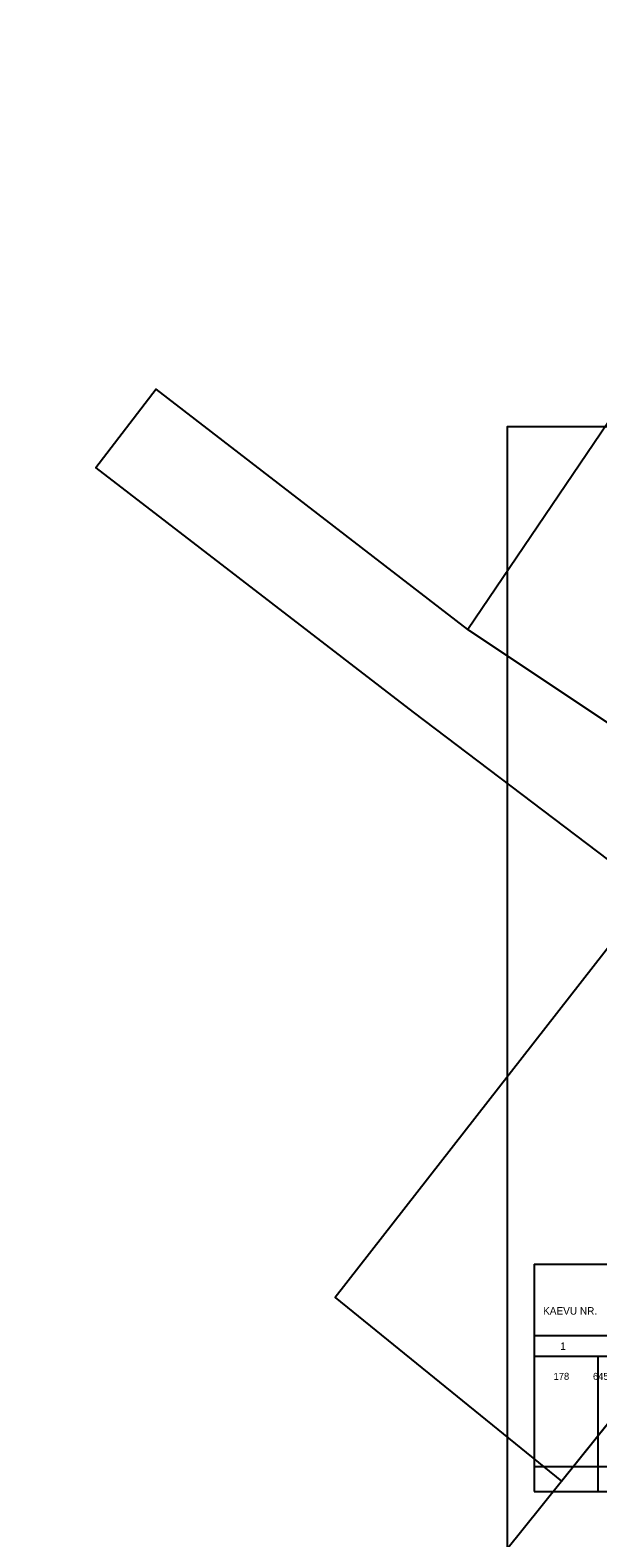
# Model space of a CAD drawing. Extents: x 640876 to 641182, y 6455704 to 6455993.
# Drawn here: x 640876.4 to 640933.2, y 6455818.5 to 6455969.2 of the extents above; entities that cross this region are included whole.
import ezdxf

# ---------------------------------------------------------------- set-up
doc = ezdxf.new("R2010")
doc.units = 0
for name, color, linetype in [('ABIJOONIS', 7, 'Continuous'), ('PIIR', 7, 'Continuous'), ('VORMISTUS', 7, 'Continuous')]:
    doc.layers.add(name, color=color, linetype=linetype)

msp = doc.modelspace()

# ---------------------------------------------------------------- linework, layer by layer
at = {"layer": 'ABIJOONIS'}
for p, q in [((640926.8, 6455845.85), (640977.48, 6455845.85)), ((640926.8, 6455845.85), (640926.8, 6455836.65)), ((640926.8, 6455838.74), (640975.11, 6455838.74)), ((640926.8, 6455836.65), (641014.84, 6455836.65)), ((640926.8, 6455836.65), (640926.8, 6455823.15)), ((640933.15, 6455836.65), (640933.15, 6455823.15)), ((640926.8, 6455825.65), (641014.8, 6455825.65)), ((640926.8, 6455825.65), (641014.8, 6455825.65)), ((640926.8, 6455823.15), (641014.8, 6455823.15))]:
    msp.add_line(p, q, dxfattribs=at)
at = {"layer": 'PIIR'}
for points in [[(640960.73, 6455969.25), (640920.16, 6455909.31), (640971.01, 6455875.38), (640993.57, 6455904.12), (640970.23, 6455922.96), (640989.11, 6455946.27)], [(640971.01, 6455875.38), (640920.16, 6455909.31), (640889.02, 6455933.34), (640882.97, 6455925.5), (640914.68, 6455901.06), (640938.5, 6455883.04), (640962.33, 6455865.02)], [(640962.33, 6455865.02), (640938.49, 6455883.03), (640906.91, 6455842.53), (640929.52, 6455824.17)]]:
    msp.add_lwpolyline(points, close=True, dxfattribs=at)
msp.add_lwpolyline([(641037.5, 6455958.58), (641024.93, 6455943.02), (641012.36, 6455927.46), (640993.57, 6455904.12), (640971.01, 6455875.38), (640962.33, 6455865.02), (640876.41, 6455757.97), (640888.17, 6455749.25), (640894.56, 6455746.37), (640902.45, 6455758.84), (640915.55, 6455775.13), (640928.34, 6455790.92), (640960.9, 6455766.7), (640964.64, 6455771.22), (640941.6, 6455788.51), (640929.99, 6455798.13), (640933.13, 6455802.02), (640952.64, 6455826.1), (640977.72, 6455857.07), (640984.64, 6455865.92), (641005.01, 6455891.09), (641032.25, 6455870.2), (641049.71, 6455856.81)], dxfattribs=at)
at = {"layer": 'VORMISTUS'}
msp.add_lwpolyline([(640924.11, 6455786.13), (640924.11, 6455929.63), (641016.61, 6455929.63), (641016.61, 6455786.13)], close=True, dxfattribs=at)

# ---------------------------------------------------------------- texts
at = {"layer": 'ABIJOONIS'}
for s, height, p in [('KAEVU NR.', 0.75, (640927.68, 6455840.82)), ('1', 0.75, (640929.4, 6455837.29)), ('178', 0.7, (640928.73, 6455834.3)), ('6455856.88', 0.7, (640932.67, 6455834.3))]:
    msp.add_text(s, height=height, dxfattribs=at).set_placement(p)

doc.saveas('drawing.dxf')
